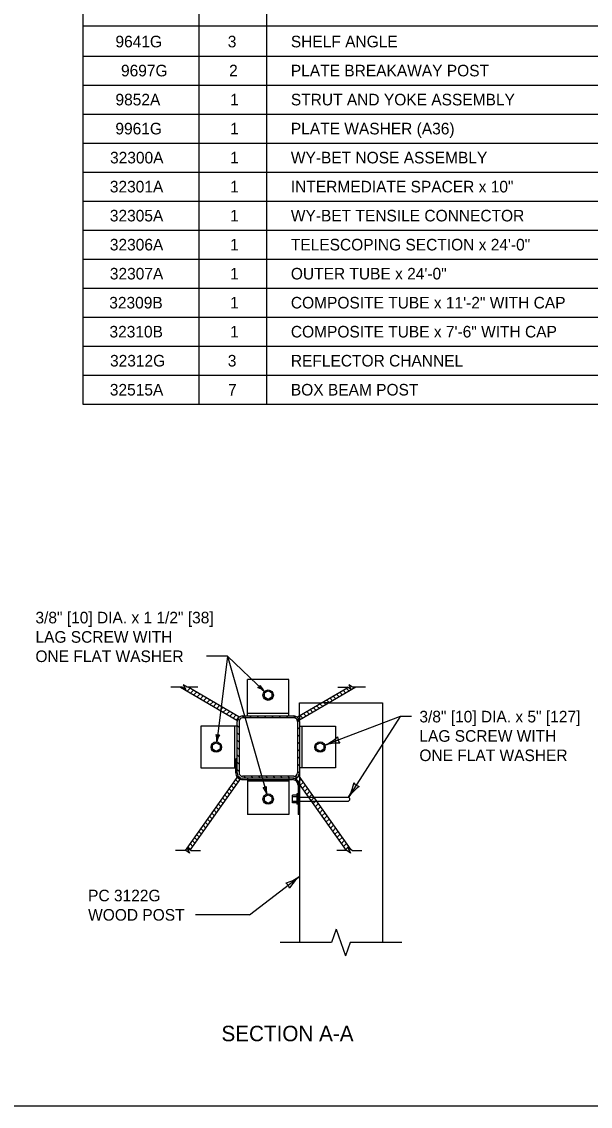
# Model space of a CAD drawing. Extents: x 49991.4 to 50021, y 49987.6 to 50011.4.
# Drawn here: x 50011.02 to 50013.97, y 49987.8 to 49993.41 of the extents above; entities that cross this region are included whole.
import ezdxf

# ---------------------------------------------------------------- set-up
doc = ezdxf.new("R2010")
doc.units = 0
for name, color, linetype in [('Level 1', 7, 'Continuous'), ('Level 2', 7, 'Continuous'), ('Level 3', 7, 'Continuous'), ('Level 4', 7, 'Continuous'), ('Level 6', 7, 'Continuous')]:
    doc.layers.add(name, color=color, linetype=linetype)

msp = doc.modelspace()

# ---------------------------------------------------------------- linework, layer by layer
at = {"layer": 'Level 1'}
for p, q in [((50012.4063, 49990.0052), (50012.1912, 49990.0052)), ((50012.1912, 49989.8171), (50012.1912, 49990.0052)), ((50012.4063, 49989.8171), (50012.4063, 49990.0052)), ((50011.8455, 49989.9653), (50012.1365, 49989.7947)), ((50011.8798, 49989.9452), (50011.8946, 49989.9599)), ((50012.1467, 49989.8121), (50011.8854, 49989.9653)), ((50011.8968, 49989.9353), (50011.9114, 49989.9501)), ((50011.9138, 49989.9253), (50011.9284, 49989.9401)), ((50012.4509, 49989.8121), (50012.7102, 49989.9642)), ((50012.7519, 49989.9653), (50012.461, 49989.7947)), ((50012.6836, 49989.9252), (50012.669, 49989.94)), ((50012.7006, 49989.9352), (50012.686, 49989.95)), ((50012.7177, 49989.9452), (50012.703, 49989.9599)), ((50011.9307, 49989.9154), (50011.9453, 49989.9302)), ((50011.9477, 49989.9054), (50011.9623, 49989.9202)), ((50011.9646, 49989.8955), (50011.9792, 49989.9103)), ((50011.9816, 49989.8855), (50011.9962, 49989.9004)), ((50011.9985, 49989.8756), (50012.0132, 49989.8904)), ((50012.0155, 49989.8657), (50012.0301, 49989.8805)), ((50012.4599, 49989.8843), (50012.574, 49989.8843)), ((50012.4599, 49989.8174), (50012.4599, 49989.8843)), ((50012.5981, 49989.8751), (50012.5835, 49989.8899)), ((50012.6152, 49989.8851), (50012.6006, 49989.8999)), ((50012.6138, 49989.8843), (50012.8899, 49989.8843)), ((50012.6323, 49989.8951), (50012.6177, 49989.9099)), ((50012.6494, 49989.9052), (50012.6348, 49989.9199)), ((50012.6665, 49989.9152), (50012.6519, 49989.93)), ((50012.8899, 49989.8843), (50012.8899, 49988.6459)), ((50012.0325, 49989.8557), (50012.0471, 49989.8705)), ((50012.0494, 49989.8458), (50012.064, 49989.8606)), ((50012.0664, 49989.8358), (50012.081, 49989.8507)), ((50012.0833, 49989.8259), (50012.0979, 49989.8407)), ((50012.1003, 49989.816), (50012.1149, 49989.8308)), ((50012.1912, 49989.8306), (50012.4063, 49989.8306)), ((50012.4956, 49989.815), (50012.4811, 49989.8298)), ((50012.5127, 49989.825), (50012.4981, 49989.8398)), ((50012.5298, 49989.835), (50012.5152, 49989.8498)), ((50012.5469, 49989.845), (50012.5323, 49989.8598)), ((50012.564, 49989.8551), (50012.5494, 49989.8699)), ((50012.5811, 49989.8651), (50012.5665, 49989.8799)), ((50012.1172, 49989.806), (50012.1319, 49989.8208)), ((50012.1365, 49989.7947), (50012.1467, 49989.8121)), ((50012.1375, 49989.523), (50012.1375, 49989.7888)), ((50012.1487, 49989.7946), (50012.141, 49989.8023)), ((50012.1743, 49989.8069), (50012.1642, 49989.8171)), ((50012.1659, 49989.8171), (50012.4316, 49989.8171)), ((50012.2123, 49989.8069), (50012.2021, 49989.8171)), ((50012.2503, 49989.8069), (50012.2401, 49989.8171)), ((50012.2883, 49989.8069), (50012.2781, 49989.8171)), ((50012.3263, 49989.8069), (50012.3161, 49989.8171)), ((50012.3643, 49989.8069), (50012.3541, 49989.8171)), ((50012.4023, 49989.8069), (50012.3921, 49989.8171)), ((50012.4599, 49989.7873), (50012.4301, 49989.8171)), ((50012.461, 49989.7947), (50012.4509, 49989.8121)), ((50012.4599, 49989.7887), (50012.4599, 49989.7966)), ((50012.4599, 49989.7887), (50012.46, 49989.523)), ((50012.4599, 49989.7887), (50012.4599, 49989.7887)), ((50012.4786, 49989.805), (50012.464, 49989.8198)), ((50012.1375, 49989.7634), (50011.9494, 49989.7634)), ((50011.9494, 49989.7634), (50011.9494, 49989.5485)), ((50012.124, 49989.7634), (50012.124, 49989.5485)), ((50012.1477, 49989.7575), (50012.1375, 49989.7677)), ((50012.1477, 49989.7195), (50012.1375, 49989.7297)), ((50012.4599, 49989.7493), (50012.4496, 49989.7596)), ((50012.4599, 49989.7113), (50012.4497, 49989.7216)), ((50012.4599, 49989.7634), (50012.6479, 49989.7634)), ((50012.4733, 49989.7634), (50012.4733, 49989.5485)), ((50012.6479, 49989.7634), (50012.6479, 49989.5485)), ((50012.1477, 49989.6815), (50012.1375, 49989.6917)), ((50012.4599, 49989.6733), (50012.4497, 49989.6836)), ((50012.1477, 49989.6435), (50012.1375, 49989.6537)), ((50012.1477, 49989.6055), (50012.1375, 49989.6157)), ((50012.4599, 49989.6353), (50012.4497, 49989.6456)), ((50012.46, 49989.5973), (50012.4497, 49989.6076)), ((50011.9494, 49989.5485), (50012.1375, 49989.5485)), ((50012.1308, 49989.523), (50012.1308, 49989.5485)), ((50012.1477, 49989.5675), (50012.1375, 49989.5777)), ((50012.46, 49989.5593), (50012.4497, 49989.5695)), ((50012.6479, 49989.5485), (50012.46, 49989.5485)), ((50012.1412, 49989.5057), (50011.8688, 49989.1208)), ((50011.8952, 49989.1233), (50012.1576, 49989.4941)), ((50012.1438, 49989.4745), (50012.1293, 49989.4889)), ((50012.1477, 49989.5295), (50012.1375, 49989.5397)), ((50012.155, 49989.4903), (50012.1405, 49989.5047)), ((50012.1576, 49989.4941), (50012.1412, 49989.5057)), ((50012.4316, 49989.4947), (50012.1659, 49989.4947)), ((50012.1659, 49989.488), (50012.1912, 49989.488)), ((50012.1825, 49989.4947), (50012.1722, 49989.505)), ((50012.1912, 49989.4947), (50012.1912, 49989.3066)), ((50012.2205, 49989.4947), (50012.2102, 49989.505)), ((50012.2585, 49989.4947), (50012.2483, 49989.505)), ((50012.2965, 49989.4947), (50012.2863, 49989.505)), ((50012.3345, 49989.4947), (50012.3243, 49989.505)), ((50012.3725, 49989.4947), (50012.3623, 49989.505)), ((50012.4105, 49989.4947), (50012.4003, 49989.505)), ((50012.4063, 49989.4947), (50012.4063, 49989.3066)), ((50012.4063, 49989.488), (50012.4249, 49989.488)), ((50012.4453, 49989.4979), (50012.4374, 49989.5059)), ((50012.4399, 49989.4941), (50012.4565, 49989.5058)), ((50012.7039, 49989.1208), (50012.4399, 49989.4941)), ((50012.4426, 49989.4903), (50012.4572, 49989.5049)), ((50012.4599, 49989.5213), (50012.4497, 49989.5315)), ((50012.4538, 49989.4745), (50012.4683, 49989.4891)), ((50012.4565, 49989.5058), (50012.7259, 49989.1249)), ((50012.4599, 49989.5222), (50012.4599, 49989.501)), ((50012.1102, 49989.4271), (50012.0958, 49989.4415)), ((50012.1214, 49989.4429), (50012.107, 49989.4573)), ((50012.1326, 49989.4587), (50012.1182, 49989.4731)), ((50012.1912, 49989.4813), (50012.4063, 49989.4813)), ((50012.4532, 49989.4596), (50012.4532, 49989.3066)), ((50012.4599, 49989.4658), (50012.4599, 49988.6459)), ((50012.465, 49989.4587), (50012.4795, 49989.4733)), ((50012.4761, 49989.4429), (50012.4907, 49989.4575)), ((50012.4873, 49989.4271), (50012.5019, 49989.4416)), ((50012.0655, 49989.3639), (50012.051, 49989.3782)), ((50012.0767, 49989.3797), (50012.0622, 49989.394)), ((50012.0879, 49989.3955), (50012.0734, 49989.4098)), ((50012.099, 49989.4113), (50012.0846, 49989.4256)), ((50012.4464, 49989.4067), (50012.4239, 49989.4067)), ((50012.4239, 49989.3677), (50012.4239, 49989.4067)), ((50012.4464, 49989.3992), (50012.4239, 49989.3992)), ((50012.4464, 49989.4141), (50012.4464, 49989.3604)), ((50012.4532, 49989.4141), (50012.4464, 49989.4141)), ((50012.4985, 49989.4113), (50012.5131, 49989.4258)), ((50012.5097, 49989.3955), (50012.5243, 49989.41)), ((50012.5209, 49989.3796), (50012.5354, 49989.3942)), ((50012.5321, 49989.3638), (50012.5466, 49989.3784)), ((50012.0319, 49989.3164), (50012.0175, 49989.3308)), ((50012.0431, 49989.3322), (50012.0286, 49989.3466)), ((50012.0543, 49989.3481), (50012.0398, 49989.3624)), ((50012.4464, 49989.3752), (50012.4239, 49989.3752)), ((50012.4464, 49989.3677), (50012.4239, 49989.3677)), ((50012.4532, 49989.3604), (50012.4464, 49989.3604)), ((50012.5433, 49989.348), (50012.5578, 49989.3626)), ((50012.5544, 49989.3322), (50012.569, 49989.3468)), ((50012.5656, 49989.3164), (50012.5802, 49989.3309)), ((50011.9871, 49989.2532), (50011.9727, 49989.2675)), ((50011.9983, 49989.269), (50011.9839, 49989.2834)), ((50012.0095, 49989.2848), (50011.9951, 49989.2992)), ((50012.0207, 49989.3006), (50012.0063, 49989.315)), ((50012.4063, 49989.3066), (50012.1912, 49989.3066)), ((50012.4599, 49989.3066), (50012.4532, 49989.3066)), ((50012.5768, 49989.3006), (50012.5914, 49989.3151)), ((50012.588, 49989.2847), (50012.6026, 49989.2993)), ((50012.5992, 49989.2689), (50012.6137, 49989.2835)), ((50012.6104, 49989.2531), (50012.6249, 49989.2677)), ((50011.9536, 49989.2058), (50011.9391, 49989.2201)), ((50011.9648, 49989.2216), (50011.9503, 49989.2359)), ((50011.976, 49989.2374), (50011.9615, 49989.2517)), ((50012.6215, 49989.2373), (50012.6361, 49989.2519)), ((50012.6327, 49989.2215), (50012.6473, 49989.236)), ((50012.6439, 49989.2057), (50012.6585, 49989.2202)), ((50011.9088, 49989.1425), (50011.8944, 49989.1569)), ((50011.92, 49989.1583), (50011.9056, 49989.1727)), ((50011.9312, 49989.1741), (50011.9167, 49989.1885)), ((50011.9424, 49989.19), (50011.9279, 49989.2043)), ((50012.6551, 49989.1899), (50012.6697, 49989.2044)), ((50012.6663, 49989.174), (50012.6808, 49989.1886)), ((50012.6775, 49989.1582), (50012.692, 49989.1728)), ((50012.6887, 49989.1424), (50012.7032, 49989.157)), ((50011.8976, 49989.1267), (50011.8832, 49989.1411)), ((50012.6998, 49989.1266), (50012.7144, 49989.1412))]:
    msp.add_line(p, q, dxfattribs=at)
for points in [[(49999.3835, 49998.9992), (50016.7501, 49998.9992), (50016.7501, 49987.7988), (49999.3835, 49987.7988)], [(50012.2792, 49989.9133), (50012.2792, 49989.9358), (50012.2987, 49989.9472), (50012.3182, 49989.9358), (50012.3182, 49989.9133), (50012.2987, 49989.9021)], [(50012.0105, 49989.6447), (50012.0105, 49989.6672), (50012.03, 49989.6784), (50012.0495, 49989.6672), (50012.0495, 49989.6447), (50012.03, 49989.6333)], [(50012.5478, 49989.6447), (50012.5478, 49989.6672), (50012.5673, 49989.6784), (50012.5868, 49989.6672), (50012.5868, 49989.6447), (50012.5673, 49989.6333)], [(50012.2792, 49989.376), (50012.2792, 49989.3985), (50012.2987, 49989.4097), (50012.3182, 49989.3985), (50012.3182, 49989.376), (50012.2987, 49989.3646)]]:
    msp.add_lwpolyline(points, close=True, dxfattribs=at)
for points in [[(50012.1477, 49989.7888), (50012.1477, 49989.5231)], [(50012.4316, 49989.8069), (50012.1658, 49989.8069)], [(50012.4496, 49989.7888), (50012.4497, 49989.523)], [(50012.4316, 49989.505), (50012.1658, 49989.505)]]:
    msp.add_lwpolyline(points, dxfattribs=at)
for centre in [(50012.2987, 49989.9246), (50012.0301, 49989.6559), (50012.5674, 49989.6559), (50012.2987, 49989.3872)]:
    msp.add_circle(centre, 0.0269, dxfattribs=at)
for centre, radius, start, end in [((50012.1659, 49989.7888), 0.0283, 90, 180), ((50012.1658, 49989.7888), 0.0181, 90, 180), ((50012.4316, 49989.7888), 0.0181, 0, 90), ((50012.1659, 49989.523), 0.0351, 180, 217.977), ((50012.1659, 49989.523), 0.0283, 180, 270), ((50012.1658, 49989.5231), 0.0181, 180, 270), ((50012.1659, 49989.523), 0.0351, 251.2654, 270), ((50012.4249, 49989.4596), 0.0283, 359.9026, 90), ((50012.4249, 49989.4596), 0.0351, 58.6547, 88.848), ((50012.4316, 49989.523), 0.0181, 270, 0), ((50012.4316, 49989.523), 0.0283, 270, 0), ((50012.4249, 49989.4596), 0.0351, 1.4186, 11.8816)]:
    msp.add_arc(centre, radius, start, end, dxfattribs=at)
msp.add_ellipse((50012.4316, 49989.7887), major_axis=(0, 0.0284), ratio=0.997077, start_param=4.712389, end_param=6.283185, dxfattribs=at)
at = {"layer": 'Level 2'}
for p, q in [((50011.3397, 49998.8342), (50011.3397, 49991.4286)), ((50011.9397, 49998.6342), (50011.9397, 49991.4286)), ((50012.2897, 49998.6342), (50012.2897, 49991.4286)), ((50011.3397, 49993.3842), (50016.5707, 49993.3842)), ((50011.3397, 49993.2286), (50016.5707, 49993.2286)), ((50011.3397, 49993.0786), (50016.5707, 49993.0786)), ((50011.3397, 49992.9286), (50016.5707, 49992.9286)), ((50011.3397, 49992.7786), (50016.5707, 49992.7786)), ((50011.3397, 49992.6286), (50016.5707, 49992.6286)), ((50011.3397, 49992.4786), (50016.5707, 49992.4786)), ((50011.3397, 49992.3286), (50016.5707, 49992.3286)), ((50011.3397, 49992.1786), (50016.5707, 49992.1786)), ((50011.3397, 49992.0286), (50016.5707, 49992.0286)), ((50011.3397, 49991.8786), (50016.5707, 49991.8786)), ((50011.3397, 49991.7286), (50016.5707, 49991.7286)), ((50011.3397, 49991.5786), (50016.5707, 49991.5786)), ((50011.3397, 49991.4286), (50016.5707, 49991.4286))]:
    msp.add_line(p, q, dxfattribs=at)
at = {"layer": 'Level 3'}
for p, q in [((50012.0875, 49990.1255), (50012.0333, 49989.6826)), ((50012.0875, 49990.1255), (50012.2914, 49989.413)), ((50012.0875, 49990.1255), (50012.2793, 49989.9431)), ((50012.9809, 49989.8135), (50012.5925, 49989.6655)), ((50012.9809, 49989.8135), (50012.7151, 49989.3972)), ((50013.0412, 49989.8135), (50012.9809, 49989.8135)), ((50012.2025, 49988.7886), (50012.4599, 49988.9867)), ((50012.6506, 49988.7145), (50012.6263, 49988.6459)), ((50012.6506, 49988.7145), (50012.6749, 49988.6459)), ((50012.6263, 49988.6459), (50012.3599, 49988.6459)), ((50012.6749, 49988.6459), (50012.6992, 49988.5773)), ((50012.7235, 49988.6459), (50012.6992, 49988.5773)), ((50012.9899, 49988.6459), (50012.7235, 49988.6459))]:
    msp.add_line(p, q, dxfattribs=at)
for points in [[(50012.0875, 49990.1255), (50011.9798, 49990.1255)], [(50012.2025, 49988.7886), (50011.9217, 49988.7886)]]:
    msp.add_lwpolyline(points, dxfattribs=at)
for centre, radius, start, end in [((50012.2328, 49989.9873), 0.0274, 298.5774, 334.2998), ((50012.206, 49989.8595), 0.1111, 48.7991, 68.9826), ((50012.3636, 49990.0234), 0.1165, 204.3614, 223.6113), ((50011.9225, 49989.6915), 0.1111, 355.3923, 15.5758), ((50012.041, 49989.7462), 0.0274, 245.1706, 280.893), ((50012.148, 49989.6628), 0.1165, 150.9547, 170.2045), ((50012.4989, 49989.8789), 0.233, 293.6867, 312.9365), ((50012.6631, 49989.4547), 0.2223, 88.3154, 108.4989), ((50012.7123, 49989.7111), 0.0548, 182.9982, 218.7205), ((50012.2737, 49989.4747), 0.0274, 268.1102, 303.8326), ((50012.1859, 49989.3781), 0.1111, 18.3319, 38.5154), ((50012.4048, 49989.4395), 0.1165, 173.8943, 193.1441), ((50012.5128, 49989.5127), 0.233, 330.2698, 349.5197), ((50012.8974, 49989.2699), 0.2223, 124.8985, 145.082), ((50012.7841, 49989.5053), 0.0548, 219.5813, 255.3037), ((50012.3317, 49989.1683), 0.2223, 285.0386, 305.2221), ((50012.611, 49988.8093), 0.233, 130.4099, 149.6597), ((50012.3583, 49988.9085), 0.0548, 19.7214, 55.4438)]:
    msp.add_arc(centre, radius, start, end, dxfattribs=at)
at = {"layer": 'Level 4'}
for p, q in [((50012.6138, 49989.8843), (50012.574, 49989.8843)), ((50012.4599, 49989.8174), (50012.4599, 49989.7966)), ((50012.1375, 49989.5955), (50012.1308, 49989.5955)), ((50012.1308, 49989.5955), (50012.1308, 49989.5485)), ((50012.1912, 49989.488), (50012.4063, 49989.488)), ((50012.4599, 49989.501), (50012.4599, 49989.4658)), ((50012.4532, 49989.3972), (50012.7151, 49989.3972)), ((50012.4532, 49989.3771), (50012.7151, 49989.3771)), ((50012.7218, 49989.3905), (50012.7151, 49989.3972)), ((50012.7151, 49989.3771), (50012.7218, 49989.3838)), ((50012.7218, 49989.3838), (50012.7218, 49989.3905))]:
    msp.add_line(p, q, dxfattribs=at)
for centre, start, end in [((50012.1659, 49989.523), 217.977, 251.2694), ((50012.4249, 49989.4596), 11.8816, 58.6547)]:
    msp.add_arc(centre, 0.0351, start, end, dxfattribs=at)
at = {"layer": 'Level 6'}
for p, q in [((50011.8516, 49989.9653), (50011.7955, 49989.9653)), ((50011.8719, 49989.953), (50011.8516, 49989.9653)), ((50011.8789, 49989.9653), (50011.8588, 49989.9777)), ((50011.8588, 49989.9777), (50011.8719, 49989.953)), ((50011.9354, 49989.9653), (50011.8789, 49989.9653)), ((50012.6583, 49989.9653), (50012.7083, 49989.9653)), ((50012.7285, 49989.953), (50012.7083, 49989.9653)), ((50012.7356, 49989.9653), (50012.7154, 49989.9777)), ((50012.7154, 49989.9777), (50012.7285, 49989.953)), ((50012.8019, 49989.9653), (50012.7356, 49989.9653)), ((50011.8719, 49989.1208), (50011.8188, 49989.1208)), ((50011.8921, 49989.1084), (50011.8719, 49989.1208)), ((50011.8992, 49989.1208), (50011.879, 49989.1331)), ((50011.879, 49989.1331), (50011.8921, 49989.1084)), ((50011.8992, 49989.1208), (50011.9492, 49989.1208)), ((50012.7052, 49989.1208), (50012.6539, 49989.1208)), ((50012.7255, 49989.1084), (50012.7052, 49989.1208)), ((50012.7326, 49989.1208), (50012.7124, 49989.1331)), ((50012.7124, 49989.1331), (50012.7255, 49989.1084)), ((50012.7326, 49989.1208), (50012.7826, 49989.1208))]:
    msp.add_line(p, q, dxfattribs=at)

# ---------------------------------------------------------------- texts
at = {"layer": 'Level 2'}
for s, height, p in [(' 9641G', 0.06, (50011.4861, 49993.2736)), ('3', 0.06, (50012.0895, 49993.2736)), ('SHELF ANGLE', 0.06, (50012.4161, 49993.2736)), ('9697G', 0.06, (50011.5371, 49993.1236)), ('2', 0.06, (50012.0964, 49993.1236)), ('PLATE BREAKAWAY POST', 0.06, (50012.4161, 49993.1236)), (' 9852A', 0.06, (50011.4862, 49992.9736)), ('1', 0.06, (50012.1018, 49992.9736)), ('STRUT AND YOKE ASSEMBLY', 0.06, (50012.4161, 49992.9736)), ('9961G', 0.06, (50011.5081, 49992.8236)), ('1', 0.06, (50012.1018, 49992.8236)), ('PLATE WASHER (A36)', 0.06, (50012.4161, 49992.8236)), ('32300A', 0.06, (50011.4803, 49992.6736)), ('1', 0.06, (50012.1018, 49992.6736)), ('WY-BET NOSE ASSEMBLY', 0.06, (50012.4161, 49992.6736)), ('32301A', 0.06, (50011.4793, 49992.5236)), ('1', 0.06, (50012.1018, 49992.5236)), ('INTERMEDIATE SPACER x 10"', 0.06, (50012.4161, 49992.5236)), ('32305A', 0.06, (50011.4793, 49992.3736)), ('1', 0.06, (50012.1018, 49992.3736)), ('WY-BET TENSILE CONNECTOR', 0.06, (50012.4161, 49992.3736)), ('32306A', 0.06, (50011.4793, 49992.2236)), ('1', 0.06, (50012.1018, 49992.2236)), ('TELESCOPING SECTION x 24\'-0"', 0.06, (50012.4161, 49992.2236)), ('32307A', 0.06, (50011.4793, 49992.0736)), ('1', 0.06, (50012.1018, 49992.0736)), ('OUTER TUBE x 24\'-0"', 0.06, (50012.4161, 49992.0736)), ('32309B', 0.06, (50011.4763, 49991.9236)), ('1', 0.06, (50012.1018, 49991.9236)), ('COMPOSITE TUBE x 11\'-2" WITH CAP', 0.06, (50012.4161, 49991.9236)), ('32310B', 0.06, (50011.4773, 49991.7736)), ('1', 0.06, (50012.1018, 49991.7736)), ('COMPOSITE TUBE x 7\'-6" WITH CAP', 0.06, (50012.4161, 49991.7736)), ('32312G', 0.06, (50011.4802, 49991.6236)), ('3', 0.06, (50012.0895, 49991.6236)), ('REFLECTOR CHANNEL', 0.06, (50012.4161, 49991.6236)), ('32515A', 0.06, (50011.4793, 49991.4736)), ('7', 0.06, (50012.091, 49991.4736)), ('BOX BEAM POST', 0.06, (50012.4161, 49991.4736)), ('3/8" [10] DIA. x 1 1/2" [38]', 0.06, (50011.0943, 49990.2955)), ('LAG SCREW WITH', 0.06, (50011.0943, 49990.1955)), ('ONE FLAT WASHER', 0.06, (50011.0943, 49990.0955)), ('3/8" [10] DIA. x 5" [127]', 0.06, (50013.0812, 49989.7835)), ('LAG SCREW WITH', 0.06, (50013.0812, 49989.6835)), ('ONE FLAT WASHER', 0.06, (50013.0812, 49989.5835)), ('PC 3122G ', 0.06, (50011.3668, 49988.8586)), ('WOOD POST', 0.06, (50011.3668, 49988.7586)), ('SECTION A-A', 0.08, (50012.0569, 49988.1352))]:
    msp.add_text(s, height=height, dxfattribs=at).set_placement(p)

doc.saveas('drawing.dxf')
